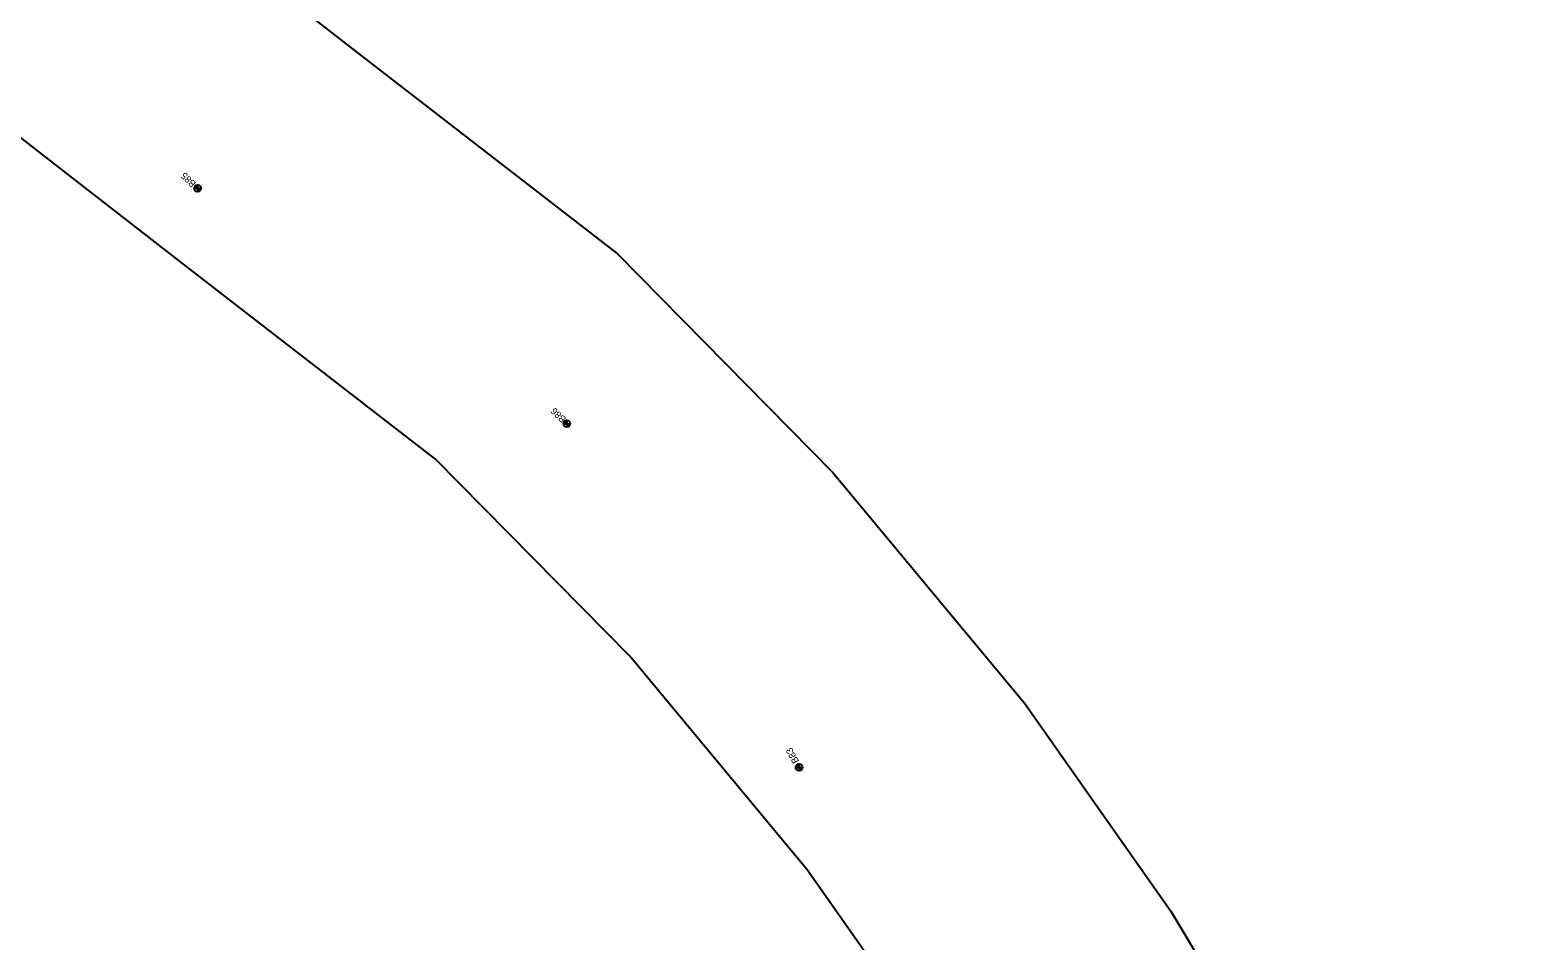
# Model space of a CAD drawing. Extents: x 327762 to 372792, y 127949 to 259367.
# Drawn here: x 358114 to 360318, y 176762 to 178093 of the extents above; entities that cross this region are included whole.
import ezdxf

# ---------------------------------------------------------------- set-up
doc = ezdxf.new("R2010")
doc.units = 0
for name, color, linetype in [('E_SOIL_BORE1 [KAPUR_CADDS_LEVELS]', 7, 'Continuous'), ('E_SOIL_BORE2 [KAPUR_CADDS_LEVELS]', 7, 'Continuous'), ('P_MARK', 7, 'Continuous'), ('P_TC', 7, 'Continuous')]:
    doc.layers.add(name, color=color, linetype=linetype)

msp = doc.modelspace()

# ---------------------------------------------------------------- linework, layer by layer
at = {"layer": 'P_MARK'}
for p, q in [((358353.8, 177861.6), (358363.8, 177861.6)), ((358358.8, 177866.6), (358358.8, 177856.6)), ((358893.7, 177517.5), (358903.7, 177517.5)), ((358898.7, 177522.5), (358898.7, 177512.5)), ((359233.3, 177015.2), (359243.3, 177015.2)), ((359238.3, 177020.2), (359238.3, 177010.2))]:
    msp.add_line(p, q, dxfattribs=at)
for centre in [(358358.8, 177861.6), (358898.7, 177517.5), (359238.3, 177015.2)]:
    msp.add_circle(centre, 5, dxfattribs=at)
for centre, radius, start, end in [((358358.8, 177861.6), 4.5, 89.9869, 179.9869), ((358358.8, 177861.6), 4, 89.9869, 179.9869), ((358358.8, 177861.6), 3.5, 89.9869, 179.9869), ((358358.8, 177861.6), 3, 89.9869, 179.9869), ((358358.8, 177861.6), 2.5, 89.9869, 179.9869), ((358358.8, 177861.6), 2, 89.9869, 179.9869), ((358358.8, 177861.6), 1.5, 89.9869, 179.9869), ((358358.8, 177861.6), 1, 89.9869, 179.9869), ((358358.8, 177861.6), 0.5, 89.9869, 179.9869), ((358358.8, 177861.6), 4.5, 269.9869, 359.9869), ((358358.8, 177861.6), 4, 269.9869, 359.9869), ((358358.8, 177861.6), 3.5, 269.9869, 359.9869), ((358358.8, 177861.6), 3, 269.9869, 359.9869), ((358358.8, 177861.6), 2.5, 269.9869, 359.9869), ((358358.8, 177861.6), 2, 269.9869, 359.9869), ((358358.8, 177861.6), 1.5, 269.9869, 359.9869), ((358358.8, 177861.6), 1, 269.9869, 359.9869), ((358358.8, 177861.6), 0.5, 269.9869, 359.9869), ((358898.7, 177517.5), 4.5, 89.9869, 179.9869), ((358898.7, 177517.5), 4, 89.9869, 179.9869), ((358898.7, 177517.5), 3.5, 89.9869, 179.9869), ((358898.7, 177517.5), 3, 89.9869, 179.9869), ((358898.7, 177517.5), 2.5, 89.9869, 179.9869), ((358898.7, 177517.5), 2, 89.9869, 179.9869), ((358898.7, 177517.5), 1.5, 89.9869, 179.9869), ((358898.7, 177517.5), 1, 89.9869, 179.9869), ((358898.7, 177517.5), 0.5, 89.9869, 179.9869), ((358898.7, 177517.5), 4.5, 269.9869, 359.9869), ((358898.7, 177517.5), 4, 269.9869, 359.9869), ((358898.7, 177517.5), 3.5, 269.9869, 359.9869), ((358898.7, 177517.5), 3, 269.9869, 359.9869), ((358898.7, 177517.5), 2.5, 269.9869, 359.9869), ((358898.7, 177517.5), 2, 269.9869, 359.9869), ((358898.7, 177517.5), 1.5, 269.9869, 359.9869), ((358898.7, 177517.5), 1, 269.9869, 359.9869), ((358898.7, 177517.5), 0.5, 269.9869, 359.9869), ((359238.3, 177015.2), 4.5, 89.9869, 179.9869), ((359238.3, 177015.2), 4, 89.9869, 179.9869), ((359238.3, 177015.2), 3.5, 89.9869, 179.9869), ((359238.3, 177015.2), 3, 89.9869, 179.9869), ((359238.3, 177015.2), 2.5, 89.9869, 179.9869), ((359238.3, 177015.2), 2, 89.9869, 179.9869), ((359238.3, 177015.2), 1.5, 89.9869, 179.9869), ((359238.3, 177015.2), 1, 89.9869, 179.9869), ((359238.3, 177015.2), 0.5, 89.9869, 179.9869), ((359238.3, 177015.2), 4.5, 269.9869, 359.9869), ((359238.3, 177015.2), 4, 269.9869, 359.9869), ((359238.3, 177015.2), 3.5, 269.9869, 359.9869), ((359238.3, 177015.2), 3, 269.9869, 359.9869), ((359238.3, 177015.2), 2.5, 269.9869, 359.9869), ((359238.3, 177015.2), 2, 269.9869, 359.9869), ((359238.3, 177015.2), 1.5, 269.9869, 359.9869), ((359238.3, 177015.2), 1, 269.9869, 359.9869), ((359238.3, 177015.2), 0.5, 269.9869, 359.9869)]:
    msp.add_arc(centre, radius, start, end, dxfattribs=at)
at = {"layer": 'P_TC'}
for points in [[(356010.7, 184791.4), (356404.2, 181123.3), (356466.9, 180787.9), (356513.6, 180550.2), (356602.1, 180279.7), (356741, 179932.9), (356921, 179635), (357119.9, 179365.3), (357302.9, 179137.3), (357638, 178834.1), (357970.9, 178543), (358585.9, 178064.8), (358972.8, 177765.7), (359287.4, 177446.4), (359568.2, 177108.6), (359781.6, 176804.9), (359973.6, 176484.4), (360151.9, 176070.5), (360266.6, 175727.9), (360318.3, 175542.9)], [(359933.1, 175435.2), (359884.1, 175610.5), (359777.9, 175927.7), (359616.8, 176301.7), (359446, 176586.9), (359250.3, 176865.3), (358990.6, 177177.7), (358706.9, 177465.7), (358340.8, 177748.6), (357716.2, 178234.3), (357372.1, 178535.2), (357010.9, 178862.1), (356802.9, 179121.3), (356588.2, 179412.3), (356381.8, 179753.9), (356226, 180143), (356125.8, 180449.1), (356074, 180712.7), (356008.1, 181065.2), (355612.9, 184748.7)]]:
    msp.add_lwpolyline(points, dxfattribs=at)

# ---------------------------------------------------------------- texts
at = {"layer": 'E_SOIL_BORE1 [KAPUR_CADDS_LEVELS]'}
msp.add_text('B83', height=10, rotation=118.6843, dxfattribs=at).set_placement((359238.6, 177024.1))
at = {"layer": 'E_SOIL_BORE2 [KAPUR_CADDS_LEVELS]'}
for s, p in [('B85', (358357.4, 177869.4)), ('B86', (358898.3, 177525.3))]:
    msp.add_text(s, height=10, rotation=136.1942, dxfattribs=at).set_placement(p)

doc.saveas('drawing.dxf')
